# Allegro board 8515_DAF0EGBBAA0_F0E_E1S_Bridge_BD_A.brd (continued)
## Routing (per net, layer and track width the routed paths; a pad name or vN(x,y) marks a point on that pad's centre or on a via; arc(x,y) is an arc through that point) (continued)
SMB_MB_CPLD_BIC_SCL: length 7
  TOP w0.109: U35.R15 v4(133.01,32.9)
  BOTTOM w0.109: R209.2 137.52,30.99 136.31,30.99 135.81,30.48 R605.2 135.36,30.48 v1(134.61,31.22) 134.6,31.23 134.6,31.31 v4(133.01,32.9)
SMB_MB_CPLD_BIC_SDA: length 10.3
  TOP w0.109: U35.P12 v4(130.62,33.7)
  BOTTOM w0.109: R210.2 137.52,32 136.25,32 R608.2 135.03,31.5 134.82,31.71 134.57,31.71 134.23,32.05 134.23,33.09 133.21,34.1 131.02,34.1 v4(130.62,33.7)
SMB_MB_CPLD_SCL: length 9.9
  IN1 w0.124: v3(138.38,26.89) 138.47,26.98 138.47,27.27 137.97,27.76 137.97,28.06 138.17,28.26 138.91,28.26 139.03,28.39 139.03,28.99 138.91,29.11 138.01,29.11 137.88,29.23 137.88,29.7 137.98,29.79 139.12,29.79 v3(139.45,30.12)
  BOTTOM w0.109: v1(140.18,30.47) 140.01,30.3 139.63,30.3 v3(139.45,30.12) 139.09,30.48 R209.1 ; R401.1 137.33,27.09 138.19,27.09 v3(138.38,26.89)
SMB_MB_CPLD_SCL_R: length 4.1
  BOTTOM w0.109: R796.2 R401.2 137.05,25.93 R411.1 137.05,24.88 136.69,24.52 136.69,23.72 136.58,23.61 Q1.4
SMB_MB_CPLD_SDA: length 11
  IN1 w0.124: v3(134.46,28.86) 135.53,28.86 136.64,29.97 137.46,29.97 137.72,30.24 138.43,30.24 138.96,30.77 v3(139.52,30.77)
  BOTTOM w0.109: v3(139.52,30.77) 139.52,31.08 140.02,31.58 ; R210.1 138.91,31.58 140.02,31.58 ; R400.1 134.36,26.77 134.95,27.35 134.95,28.37 v3(134.46,28.86) ; 140.02,31.58 v1(140.19,31.75)
SMB_MB_CPLD_SDA_R: length 7.9
  BOTTOM w0.109: R795.2 R400.2 133.94,25.64 132.99,25.64 132.76,25.41 v1(132.76,25.13) 133.73,25.13 R410.1 133.94,24.64 134.35,24.23 134.73,24.23 134.84,24.12 134.84,23.05 134.62,22.52 134.21,22.11 Q1.1
SMB_MBBIC_BIC_R_SCL: length 3.8
  TOP w0.109: R680.1 135.38,34.54 135.25,34.67 135.25,35.79 134.8,36.24 v4(134.7,36.24) 134.67,36.22 133.95,36.22 133.66,36.5 U35.L16
SMB_MBBIC_BIC_R_SDA: length 3.3
  TOP w0.109: R681.1 135.74,35.86 134.23,37.37 v3(134.11,37.37) 134.04,37.37 133.96,37.3 U35.K16
SMB_SENSOR_SCL: length 105.6
  TOP w0.109: v3(118.49,61.47) 118.8,61.47 119.11,61.16 R277.1 118.92,60.26 117.88,60.26 117.51,59.89 R494.1
  IN1 w0.124: v3(118.49,61.47) 119.59,62.57 138.27,62.57 140.37,60.46 140.37,57.7 140.68,57.39 140.68,54.1 139.14,50.39 139.14,41.16 140.36,39.95 143.41,39.95 145.09,38.26 145.09,35.14 145.69,34.54 145.69,31.26 145.57,31.14 v3(144.9,31.14)
  BOTTOM w0.109: R290.1 95.43,48.77 100.15,44.04 105.89,44.04 109.2,47.35 109.2,48.53 109.78,49.11 111.83,49.11 113.38,50.66 113.38,52.37 115.61,54.6 116.08,54.79 116.53,55.09 117,55.57 117.33,56.37 117.33,60.6 118.2,61.47 v3(118.49,61.47) ; v3(144.9,31.14) 142.25,31.14 140.48,29.38 139.94,29.38 139.81,29.24 139.35,29.24 138.83,28.73 R584.1
SMB_SENSOR_SDA: length 243.7
  TOP w0.109: v3(39.88,13.46) 40.13,13.46 40.74,14.07 40.74,15.95 40.23,16.46 40.23,17.88 36.58,21.54 R493.1 ; R278.1 117.84,62.07 118.01,61.89 118.01,61.1 v3(118.36,60.75)
  IN1 w0.124: v3(108.08,15.62) 107.92,15.62 104.7,12.39 98.26,12.39 97.48,11.61 56.36,11.61 55.54,12.43 40.91,12.43 v3(39.88,13.46) ; v3(118.36,60.75) 118.77,60.75 120.16,62.14 138.09,62.14 139.27,60.96 139.27,57.67 139.59,57.34 140.11,57.34 140.24,57.22 140.24,54.26 138.71,50.57 138.71,40.98 140.18,39.52 143.23,39.52 144.64,38.11 144.64,38.01 144.65,38 144.65,34.83 v3(145.03,34.44)
  BOTTOM w0.109: v3(145.03,34.44) 145.36,34.11 145.36,33.17 145.01,32.82 143.73,32.82 142.46,31.55 142.08,31.55 140.31,29.79 139.77,29.79 139.64,29.66 139.02,29.66 R586.1 ; v3(108.08,15.62) 108.08,15.2 107.97,15.09 106.6,15.09 106.37,15.32 106.37,18.92 111.13,23.68 111.13,25.93 112.81,27.61 113.1,28.29 113.1,32.71 113.06,32.89 111.78,35.99 109.76,38.01 109.76,44.2 111.55,45.99 111.55,46.3 115.11,49.86 115.11,51.51 116.89,53.28 117.58,53.74 118.49,54.66 118.55,54.81 118.99,55.88 118.99,55.88 119.21,56.41 119.22,56.42 119.25,56.49 119.33,56.52 119.79,56.98 120.55,56.98 121.36,57.8 121.36,60.78 120.56,61.58 119.59,61.58 118.76,60.75 v3(118.36,60.75) 117.75,60.14 117.75,56.28 117.36,55.34 116.77,54.75 116.28,54.43 115.95,54.29 113.79,52.13 113.79,50.49 111.94,48.64 109.89,48.64 109.61,48.36 109.61,47.18 106.06,43.63 104.35,43.63 104.33,43.61 99.8,43.61 v1(96.43,46.97) 95.78,47.62 R289.1
SMB_TMP75_SCL_R: length 3.3
  TOP w0.109: U16.2 93.95,48.54 93.73,48.76 v3(93.09,48.76)
  BOTTOM w0.109: R290.2 94.42,48.82 93.32,48.82 93.26,48.76 v3(93.09,48.76)
SMB_TMP75_SDA_R: length 4.2
  TOP w0.109: v3(93.6,48.13) 93.84,47.89 U16.1
  BOTTOM w0.109: R289.2 93.81,46.96 93.37,46.96 93.24,47.09 v1(93.24,47.17) 93.24,47.78 v3(93.6,48.13)
SPI_BIC_CS0_R_N: length 6.4
  TOP w0.109: U35.A7 126.27,44.55 126.27,46.33 125.75,46.85 125.75,49.91 R635.2
SPI_BIC_R_CLK: length 6.7
  TOP w0.109: U35.A5 124.62,45.91 124.21,46.31 R789.1 124.57,46.97 124.71,47.12 124.71,49.93 R785.2
SPI_BIC_R_IO1: length 7.7
  TOP w0.109: R786.1 123.7,49.93 123.7,47.48 R782.1 123.19,46.47 124.22,45.44 124.22,44.1 U35.B5
TDR_DIFF_85_BOT_DN: length 152.4
  BOTTOM w0.132: X3.4 -9.02,19.42 -9.13,19.53 -11.32,19.53 -11.71,19.14 -11.71,17.68 -12.13,17.26 -12.72,17.26 -13.14,17.68 -13.14,21.51 -13.36,21.73 -13.67,21.73 -13.89,21.51 -13.89,17.68 -14.3,17.26 -14.89,17.26 -15.31,17.68 -15.31,21.51 -15.53,21.73 -15.84,21.73 -16.06,21.51 -16.06,17.68 -16.48,17.26 -17.07,17.26 -17.49,17.68 -17.49,21.51 -17.71,21.73 -18.01,21.73 -18.23,21.51 -18.23,17.68 -18.65,17.26 -19.24,17.26 -19.66,17.68 -19.66,21.51 -19.88,21.73 -20.19,21.73 -20.41,21.51 -20.41,17.68 -20.83,17.26 -21.42,17.26 -21.84,17.68 -21.84,21.51 -22.05,21.73 -22.36,21.73 -22.58,21.51 -22.58,17.68 -23,17.26 -23.59,17.26 -24.01,17.68 -24.01,21.51 -24.23,21.73 -24.54,21.73 -24.76,21.51 -24.76,17.68 -25.17,17.26 -25.77,17.26 -26.18,17.68 -26.18,21.51 -26.4,21.73 -26.71,21.73 -26.93,21.51 -26.93,17.68 -27.35,17.26 -27.94,17.26 -28.36,17.68 -28.36,21.51 -28.58,21.73 -28.89,21.73 -29.1,21.51 -29.1,17.68 -29.52,17.26 -30.11,17.26 -30.53,17.68 -30.53,21.51 -30.75,21.73 -31.06,21.73 -31.28,21.51 -31.28,17.68 -31.7,17.26 -32.29,17.26 -32.71,17.68 -32.71,21.51 -32.93,21.73 -33.23,21.73 -33.45,21.51 -33.45,17.68 -33.87,17.26 -34.46,17.26 -34.88,17.68 -34.88,21.51 -35.1,21.73 -35.41,21.73 -35.63,21.51 -35.63,17.68 -36.05,17.26 -36.64,17.26 -37.06,17.68 -37.06,21.51 -37.27,21.73 -37.58,21.73 -37.8,21.51 -37.8,17.68 -38.22,17.26 -38.81,17.26 -39.23,17.68 -39.23,21.51 -39.45,21.73 -39.76,21.73 -39.98,21.51 -39.98,17.68 -40.39,17.26 -40.99,17.26 -41.4,17.68 -41.4,21.51 -41.62,21.73 -41.93,21.73 -42.15,21.51 -42.15,20.04 -42.66,19.53 -45.03,19.53 -45.21,19.34 X4.1
TDR_DIFF_85_BOT_DP: length 152.4
  BOTTOM w0.132: X3.1 -9.02,19.98 -9.13,19.87 -11.46,19.87 -12.05,19.28 -12.05,17.82 -12.27,17.6 -12.58,17.6 -12.8,17.82 -12.8,21.65 -13.22,22.07 -13.81,22.07 -14.23,21.65 -14.23,17.82 -14.44,17.6 -14.75,17.6 -14.97,17.82 -14.97,21.65 -15.39,22.07 -15.98,22.07 -16.4,21.65 -16.4,17.82 -16.62,17.6 -16.93,17.6 -17.15,17.82 -17.15,21.65 -17.56,22.07 -18.16,22.07 -18.57,21.65 -18.57,17.82 -18.79,17.6 -19.1,17.6 -19.32,17.82 -19.32,21.65 -19.74,22.07 -20.33,22.07 -20.75,21.65 -20.75,17.82 -20.97,17.6 -21.28,17.6 -21.5,17.82 -21.5,21.65 -21.91,22.07 -22.5,22.07 -22.92,21.65 -22.92,17.82 -23.14,17.6 -23.45,17.6 -23.67,17.82 -23.67,21.65 -24.09,22.07 -24.68,22.07 -25.1,21.65 -25.1,17.82 -25.32,17.6 -25.62,17.6 -25.84,17.82 -25.84,21.65 -26.26,22.07 -26.85,22.07 -27.27,21.65 -27.27,17.82 -27.49,17.6 -27.8,17.6 -28.02,17.82 -28.02,21.65 -28.44,22.07 -29.03,22.07 -29.45,21.65 -29.45,17.82 -29.66,17.6 -29.97,17.6 -30.19,17.82 -30.19,21.65 -30.61,22.07 -31.2,22.07 -31.62,21.65 -31.62,17.82 -31.84,17.6 -32.15,17.6 -32.37,17.82 -32.37,21.65 -32.78,22.07 -33.38,22.07 -33.79,21.65 -33.79,17.82 -34.01,17.6 -34.32,17.6 -34.54,17.82 -34.54,21.65 -34.96,22.07 -35.55,22.07 -35.97,21.65 -35.97,17.82 -36.19,17.6 -36.5,17.6 -36.71,17.82 -36.71,21.65 -37.13,22.07 -37.72,22.07 -38.14,21.65 -38.14,17.82 -38.36,17.6 -38.67,17.6 -38.89,17.82 -38.89,21.65 -39.31,22.07 -39.9,22.07 -40.32,21.65 -40.32,17.82 -40.54,17.6 -40.84,17.6 -41.06,17.82 -41.06,21.65 -41.48,22.07 -42.07,22.07 -42.49,21.65 -42.49,20.18 -42.81,19.87 -45.03,19.87 -45.21,20.05 X4.4
TDR_DIFF_85_IN1_DN: length 152.4
  IN1 w0.155: X6.4 -8.67,115.62 -8.74,115.55 -10.6,115.55 -10.75,115.69 -10.75,117.42 -11.24,117.91 -11.94,117.91 -12.43,117.42 -12.43,113.48 -12.72,113.19 -13.12,113.19 -13.41,113.48 -13.41,117.42 -13.9,117.91 -14.6,117.91 -15.1,117.42 -15.1,113.48 -15.38,113.19 -15.78,113.19 -16.07,113.48 -16.07,117.42 -16.56,117.91 -17.26,117.91 -17.76,117.42 -17.76,113.48 -18.04,113.19 -18.45,113.19 -18.73,113.48 -18.73,117.42 -19.23,117.91 -19.93,117.91 -20.42,117.42 -20.42,113.48 -20.71,113.19 -21.11,113.19 -21.39,113.48 -21.39,117.42 -21.89,117.91 -22.59,117.91 -23.08,117.42 -23.08,113.48 -23.37,113.19 -23.77,113.19 -24.06,113.48 -24.06,117.42 -24.55,117.91 -25.25,117.91 -25.74,117.42 -25.74,113.48 -26.03,113.19 -26.43,113.19 -26.72,113.48 -26.72,117.42 -27.21,117.91 -27.91,117.91 -28.41,117.42 -28.41,113.48 -28.69,113.19 -29.09,113.19 -29.38,113.48 -29.38,117.42 -29.87,117.91 -30.57,117.91 -31.07,117.42 -31.07,113.48 -31.35,113.19 -31.76,113.19 -32.04,113.48 -32.04,117.42 -32.54,117.91 -33.24,117.91 -33.73,117.42 -33.73,113.48 -34.02,113.19 -34.42,113.19 -34.7,113.48 -34.7,117.42 -35.2,117.91 -35.9,117.91 -36.39,117.42 -36.39,113.48 -36.68,113.19 -37.08,113.19 -37.36,113.48 -37.36,117.42 -37.86,117.91 -38.56,117.91 -39.05,117.42 -39.05,113.48 -39.34,113.19 -39.74,113.19 -40.03,113.48 -40.03,117.42 -40.52,117.91 -41.22,117.91 -41.72,117.42 -41.72,113.48 -42,113.19 -42.4,113.19 -42.69,113.48 -42.69,117.42 -43.18,117.91 -43.88,117.91 -44.38,117.42 -44.38,113.48 -44.66,113.19 -45.07,113.19 -45.35,113.48 -45.35,114.82 -46.08,115.55 -48.47,115.55 -48.67,115.75 X5.1
TDR_DIFF_85_IN1_DP: length 152.4
  IN1 w0.155: X5.4 -48.67,114.99 -48.47,115.19 -46.23,115.19 -45.71,114.67 -45.71,113.33 -45.21,112.83 -44.51,112.83 -44.02,113.33 -44.02,117.27 -43.73,117.55 -43.33,117.55 -43.05,117.27 -43.05,113.33 -42.55,112.83 -41.85,112.83 -41.36,113.33 -41.36,117.27 -41.07,117.55 -40.67,117.55 -40.38,117.27 -40.38,113.33 -39.89,112.83 -39.19,112.83 -38.7,113.33 -38.7,117.27 -38.41,117.55 -38.01,117.55 -37.72,117.27 -37.72,113.33 -37.23,112.83 -36.53,112.83 -36.03,113.33 -36.03,117.27 -35.75,117.55 -35.35,117.55 -35.06,117.27 -35.06,113.33 -34.57,112.83 -33.87,112.83 -33.37,113.33 -33.37,117.27 -33.09,117.55 -32.68,117.55 -32.4,117.27 -32.4,113.33 -31.9,112.83 -31.2,112.83 -30.71,113.33 -30.71,117.27 -30.43,117.55 -30.02,117.55 -29.74,117.27 -29.74,113.33 -29.24,112.83 -28.54,112.83 -28.05,113.33 -28.05,117.27 -27.76,117.55 -27.36,117.55 -27.08,117.27 -27.08,113.33 -26.58,112.83 -25.88,112.83 -25.39,113.33 -25.39,117.27 -25.1,117.55 -24.7,117.55 -24.41,117.27 -24.41,113.33 -23.92,112.83 -23.22,112.83 -22.72,113.33 -22.72,117.27 -22.44,117.55 -22.04,117.55 -21.75,117.27 -21.75,113.33 -21.26,112.83 -20.56,112.83 -20.06,113.33 -20.06,117.27 -19.78,117.55 -19.37,117.55 -19.09,117.27 -19.09,113.33 -18.6,112.83 -17.9,112.83 -17.4,113.33 -17.4,117.27 -17.12,117.55 -16.71,117.55 -16.43,117.27 -16.43,113.33 -15.93,112.83 -15.23,112.83 -14.74,113.33 -14.74,117.27 -14.45,117.55 -14.05,117.55 -13.77,117.27 -13.77,113.33 -13.27,112.83 -12.57,112.83 -12.08,113.33 -12.08,117.27 -11.79,117.55 -11.39,117.55 -11.1,117.27 -11.1,115.54 -10.75,115.19 -8.74,115.19 -8.67,115.12 X6.1
TDR_DIFF_85_IN2_DN: length 152.4
  IN2 w0.155: X7.4 -48.67,121.47 -48.47,121.27 -46.08,121.27 -45.35,120.54 -45.35,119.19 -45.07,118.91 -44.66,118.91 -44.38,119.19 -44.38,123.13 -43.88,123.63 -43.18,123.63 -42.69,123.13 -42.69,119.19 -42.4,118.91 -42,118.91 -41.72,119.19 -41.72,123.13 -41.22,123.63 -40.52,123.63 -40.03,123.13 -40.03,119.19 -39.74,118.91 -39.34,118.91 -39.05,119.19 -39.05,123.13 -38.56,123.63 -37.86,123.63 -37.36,123.13 -37.36,119.19 -37.08,118.91 -36.68,118.91 -36.39,119.19 -36.39,123.13 -35.9,123.63 -35.2,123.63 -34.7,123.13 -34.7,119.19 -34.42,118.91 -34.02,118.91 -33.73,119.19 -33.73,123.13 -33.24,123.63 -32.54,123.63 -32.04,123.13 -32.04,119.19 -31.76,118.91 -31.35,118.91 -31.07,119.19 -31.07,123.13 -30.57,123.63 -29.87,123.63 -29.38,123.13 -29.38,119.19 -29.09,118.91 -28.69,118.91 -28.41,119.19 -28.41,123.13 -27.91,123.63 -27.21,123.63 -26.72,123.13 -26.72,119.19 -26.43,118.91 -26.03,118.91 -25.74,119.19 -25.74,123.13 -25.25,123.63 -24.55,123.63 -24.06,123.13 -24.06,119.19 -23.77,118.91 -23.37,118.91 -23.08,119.19 -23.08,123.13 -22.59,123.63 -21.89,123.63 -21.39,123.13 -21.39,119.19 -21.11,118.91 -20.71,118.91 -20.42,119.19 -20.42,123.13 -19.93,123.63 -19.23,123.63 -18.73,123.13 -18.73,119.19 -18.45,118.91 -18.04,118.91 -17.76,119.19 -17.76,123.13 -17.26,123.63 -16.56,123.63 -16.07,123.13 -16.07,119.19 -15.78,118.91 -15.38,118.91 -15.1,119.19 -15.1,123.13 -14.6,123.63 -13.9,123.63 -13.41,123.13 -13.41,119.19 -13.12,118.91 -12.72,118.91 -12.43,119.19 -12.43,123.13 -11.94,123.63 -11.24,123.63 -10.75,123.13 -10.75,121.41 -10.6,121.27 -8.74,121.27 -8.67,121.34 X8.1
TDR_DIFF_85_IN2_DP: length 152.4
  IN2 w0.155: X7.1 -48.67,120.71 -48.47,120.91 -46.23,120.91 -45.71,120.39 -45.71,119.04 -45.21,118.55 -44.51,118.55 -44.02,119.04 -44.02,122.98 -43.73,123.27 -43.33,123.27 -43.05,122.98 -43.05,119.04 -42.55,118.55 -41.85,118.55 -41.36,119.04 -41.36,122.98 -41.07,123.27 -40.67,123.27 -40.38,122.98 -40.38,119.04 -39.89,118.55 -39.19,118.55 -38.7,119.04 -38.7,122.98 -38.41,123.27 -38.01,123.27 -37.72,122.98 -37.72,119.04 -37.23,118.55 -36.53,118.55 -36.03,119.04 -36.03,122.98 -35.75,123.27 -35.35,123.27 -35.06,122.98 -35.06,119.04 -34.57,118.55 -33.87,118.55 -33.37,119.04 -33.37,122.98 -33.09,123.27 -32.68,123.27 -32.4,122.98 -32.4,119.04 -31.9,118.55 -31.2,118.55 -30.71,119.04 -30.71,122.98 -30.43,123.27 -30.02,123.27 -29.74,122.98 -29.74,119.04 -29.24,118.55 -28.54,118.55 -28.05,119.04 -28.05,122.98 -27.76,123.27 -27.36,123.27 -27.08,122.98 -27.08,119.04 -26.58,118.55 -25.88,118.55 -25.39,119.04 -25.39,122.98 -25.1,123.27 -24.7,123.27 -24.41,122.98 -24.41,119.04 -23.92,118.55 -23.22,118.55 -22.72,119.04 -22.72,122.98 -22.44,123.27 -22.04,123.27 -21.75,122.98 -21.75,119.04 -21.26,118.55 -20.56,118.55 -20.06,119.04 -20.06,122.98 -19.78,123.27 -19.37,123.27 -19.09,122.98 -19.09,119.04 -18.6,118.55 -17.9,118.55 -17.4,119.04 -17.4,122.98 -17.12,123.27 -16.71,123.27 -16.43,122.98 -16.43,119.04 -15.93,118.55 -15.23,118.55 -14.74,119.04 -14.74,122.98 -14.45,123.27 -14.05,123.27 -13.77,122.98 -13.77,119.04 -13.27,118.55 -12.57,118.55 -12.08,119.04 -12.08,122.98 -11.79,123.27 -11.39,123.27 -11.1,122.98 -11.1,121.26 -10.75,120.91 -8.74,120.91 -8.67,120.84 X8.4
TDR_DIFF_85_TOP_DN: length 152.4
  TOP w0.132: X2.1 -45.21,14.34 -45.03,14.15 -42.81,14.15 -42.49,14.47 -42.49,15.94 -42.07,16.36 -41.48,16.36 -41.06,15.94 -41.06,12.1 -40.84,11.89 -40.54,11.89 -40.32,12.1 -40.32,15.94 -39.9,16.36 -39.31,16.36 -38.89,15.94 -38.89,12.1 -38.67,11.89 -38.36,11.89 -38.14,12.1 -38.14,15.94 -37.72,16.36 -37.13,16.36 -36.71,15.94 -36.71,12.1 -36.5,11.89 -36.19,11.89 -35.97,12.1 -35.97,15.94 -35.55,16.36 -34.96,16.36 -34.54,15.94 -34.54,12.1 -34.32,11.89 -34.01,11.89 -33.79,12.1 -33.79,15.94 -33.38,16.36 -32.78,16.36 -32.37,15.94 -32.37,12.1 -32.15,11.89 -31.84,11.89 -31.62,12.1 -31.62,15.94 -31.2,16.36 -30.61,16.36 -30.19,15.94 -30.19,12.1 -29.97,11.89 -29.66,11.89 -29.45,12.1 -29.45,15.94 -29.03,16.36 -28.44,16.36 -28.02,15.94 -28.02,12.1 -27.8,11.89 -27.49,11.89 -27.27,12.1 -27.27,15.94 -26.85,16.36 -26.26,16.36 -25.84,15.94 -25.84,12.1 -25.62,11.89 -25.32,11.89 -25.1,12.1 -25.1,15.94 -24.68,16.36 -24.09,16.36 -23.67,15.94 -23.67,12.1 -23.45,11.89 -23.14,11.89 -22.92,12.1 -22.92,15.94 -22.5,16.36 -21.91,16.36 -21.5,15.94 -21.5,12.1 -21.28,11.89 -20.97,11.89 -20.75,12.1 -20.75,15.94 -20.33,16.36 -19.74,16.36 -19.32,15.94 -19.32,12.1 -19.1,11.89 -18.79,11.89 -18.57,12.1 -18.57,15.94 -18.16,16.36 -17.56,16.36 -17.15,15.94 -17.15,12.1 -16.93,11.89 -16.62,11.89 -16.4,12.1 -16.4,15.94 -15.98,16.36 -15.39,16.36 -14.97,15.94 -14.97,12.1 -14.75,11.89 -14.44,11.89 -14.23,12.1 -14.23,15.94 -13.81,16.36 -13.22,16.36 -12.8,15.94 -12.8,12.1 -12.58,11.89 -12.27,11.89 -12.05,12.1 -12.05,13.56 -11.46,14.15 -9.13,14.15 -9.02,14.26 X1.4
TDR_DIFF_85_TOP_DP: length 152.4
  TOP w0.132: X1.1 -9.02,13.7 -9.13,13.81 -11.32,13.81 -11.71,13.42 -11.71,11.96 -12.13,11.55 -12.72,11.55 -13.14,11.96 -13.14,15.8 -13.36,16.02 -13.67,16.02 -13.89,15.8 -13.89,11.96 -14.3,11.55 -14.89,11.55 -15.31,11.96 -15.31,15.8 -15.53,16.02 -15.84,16.02 -16.06,15.8 -16.06,11.96 -16.48,11.55 -17.07,11.55 -17.49,11.96 -17.49,15.8 -17.71,16.02 -18.01,16.02 -18.23,15.8 -18.23,11.96 -18.65,11.55 -19.24,11.55 -19.66,11.96 -19.66,15.8 -19.88,16.02 -20.19,16.02 -20.41,15.8 -20.41,11.96 -20.83,11.55 -21.42,11.55 -21.84,11.96 -21.84,15.8 -22.05,16.02 -22.36,16.02 -22.58,15.8 -22.58,11.96 -23,11.55 -23.59,11.55 -24.01,11.96 -24.01,15.8 -24.23,16.02 -24.54,16.02 -24.76,15.8 -24.76,11.96 -25.17,11.55 -25.77,11.55 -26.18,11.96 -26.18,15.8 -26.4,16.02 -26.71,16.02 -26.93,15.8 -26.93,11.96 -27.35,11.55 -27.94,11.55 -28.36,11.96 -28.36,15.8 -28.58,16.02 -28.89,16.02 -29.1,15.8 -29.1,11.96 -29.52,11.55 -30.11,11.55 -30.53,11.96 -30.53,15.8 -30.75,16.02 -31.06,16.02 -31.28,15.8 -31.28,11.96 -31.7,11.55 -32.29,11.55 -32.71,11.96 -32.71,15.8 -32.93,16.02 -33.23,16.02 -33.45,15.8 -33.45,11.96 -33.87,11.55 -34.46,11.55 -34.88,11.96 -34.88,15.8 -35.1,16.02 -35.41,16.02 -35.63,15.8 -35.63,11.96 -36.05,11.55 -36.64,11.55 -37.06,11.96 -37.06,15.8 -37.27,16.02 -37.58,16.02 -37.8,15.8 -37.8,11.96 -38.22,11.55 -38.81,11.55 -39.23,11.96 -39.23,15.8 -39.45,16.02 -39.76,16.02 -39.98,15.8 -39.98,11.96 -40.39,11.55 -40.99,11.55 -41.4,11.96 -41.4,15.8 -41.62,16.02 -41.93,16.02 -42.15,15.8 -42.15,14.33 -42.66,13.81 -45.03,13.81 -45.21,13.63 X2.4
TDR_SE_50_OHM_BOT: length 152.5
  BOTTOM w0.109: J15.3 -35.93,29.76 -35.83,29.65 -33.5,29.65 -33.39,29.76 J15.2
TDR_SE_50_OHM_IN1: length 152.5
  IN1 w0.124: J12.3 -40.71,29.76 -40.82,29.65 -43.14,29.65 -43.25,29.76 J12.2
TDR_SE_50_OHM_IN2: length 152.5
  IN2 w0.124: J16.3 -50.57,29.76 -50.46,29.65 -48.14,29.65 -48.03,29.76 J16.2
TDR_SE_50_OHM_TOP: length 152.5
  TOP w0.109: J27.2 -57.78,29.76 -57.67,29.65 -55.35,29.65 -55.24,29.76 J27.3
TMP75_AD0: length 4.2
  TOP w0.109: R294.1 R288.2 88.7,47.47 v2(88.7,48.64) 88.79,48.54 U16.7
TMP75_AD1: length 5.7
  TOP w0.109: U16.6 89.24,49.19 89.03,49.4 v3(88.27,49.4)
  BOTTOM w0.109: R293.1 R287.2 90.05,49 89.56,49 89.15,49.4 v3(88.27,49.4)
TMP75_AD2: length 4.2
  TOP w0.109: U16.5 89.75,49.84 v3(89.1,50.5)
  BOTTOM w0.109: v3(89.1,50.5) 89.1,50.47 89.66,49.91 R286.2 R292.1
TMP75_ALERT_N_R: length 4.9
  TOP w0.109: U16.3 94.17,49.19 93.94,49.42 93.94,50.28 v3(94.12,50.46)
  BOTTOM w0.109: R295.1 93.57,49.91 v3(94.12,50.46) 94.13,50.46 94.68,49.91 R291.2
TP_CLK_100M_E1S_0_DN: length 4.5
  TOP w0.109: v2(36.83,35.56) 36.58,35.81 35.15,35.81 34.62,36.35 33.91,36.35 33.56,36.69 J4.A14
TP_CLK_100M_E1S_0_DP: length 4
  TOP w0.109: J4.A15 33.5,36.09 33.73,35.86 34.47,35.86 v2(36.06,34.28)
TP_CLK_100M_E1S_1_DN: length 6.4
  TOP w0.109: v2(63.63,36.83) 63.63,36.7 63.53,36.61 63.28,36.61 62.28,35.61 62.28,35.61 62.23,35.56 60.07,35.56 58.94,36.7 J5.A14
TP_CLK_100M_E1S_1_DP: length 3.8
  TOP w0.109: J5.A15 58.9,36.1 60.2,34.8 v2(61.59,34.8)
TP_CLK_100M_E1S_2_DN: length 3.7
  TOP w0.109: J6.A14 84.63,36.7 84.72,36.6 85.5,36.6 86.51,35.59 v2(87.07,35.59)
TP_CLK_100M_E1S_2_DP: length 4.8
  TOP w0.109: v2(87.38,33.78) 87.38,34.19 85.39,36.17 84.7,36.17 84.63,36.1 J6.A15
TP_CLK_100M_E1S_3_DN: length 2.1
  TOP w0.109: J7.A14 108.11,36.7 v3(107.48,37.33)
TP_CLK_100M_E1S_3_DP: length 4.1
  TOP w0.109: J7.A15 108.13,36.1 107.49,36.73 106.18,36.73 106.03,36.88 v3(106.03,37.33)
TP_E1S_0_MFG: length 2.8
  TOP w0.109: v3(26.42,40.31) 27,40.89 J4.B7
  BOTTOM w0.109: v1(26.21,41.02) 26.21,40.54 26.41,40.33 v3(26.42,40.31)
TP_E1S_0_RFU: length 1.9
  TOP w0.109: J4.B8 v3(27.09,40.29)
  BOTTOM w0.109: v3(27.09,40.29) 27.6,40.29 27.76,40.46 v1(27.78,40.46)
TP_E1S_1_MFG: length 5.5
  TOP w0.109: v2(48.56,41.48) 48.74,41.66 49.99,41.66 50.75,40.9 J5.B7
TP_E1S_1_RFU: length 4
  TOP w0.109: v2(49.91,40.89) 50.16,40.89 50.55,40.51 52.83,40.51 53.05,40.3 J5.B8
TP_E1S_2_MFG: length 5.2
  TOP w0.109: v2(75.31,42.8) 75.31,41.91 76.33,40.9 J6.B7
TP_E1S_2_RFU: length 4.1
  TOP w0.109: J6.B8 76.04,40.3 75.56,40.77 v2(75.31,40.77)
TP_E1S_3_MFG: length 4.7
  TOP w0.109: J7.B7 102.74,40.9 102.18,40.33 100.63,40.33 v2(100.36,40.06)
TP_E1S_3_RFU: length 5.5
  TOP w0.109: J7.B8 102.91,40.3 102.58,39.97 101.13,39.97 100.47,39.3 v2(99.64,38.96)
TP_P12V_E1S_0_PG: length 0.8
  TOP w0.109: v3(20.11,56.55) 19.71,56.95 U22.D7
TP_P12V_E1S_1_PG: length 0.8
  TOP w0.109: v3(44.63,56) 44.59,56 44.48,56.11 U23.D7
TP_P12V_E1S_2_PG: length 0.8
  TOP w0.109: U24.D7 70,55.8 v3(70.17,55.64)
TP_P12V_E1S_3_PG: length 0.8
  TOP w0.109: U25.D7 95.48,56.33 v3(95.95,55.86)
UART_BIC5_R_RXD: length 55.4
  TOP w0.109: J1.3 141.86,31.69 141.75,31.8 141.64,31.8 v3(141.57,31.86) ; v3(135.71,54.49) 135.42,54.2 134.99,54.2 134.05,53.26 134.05,52.28 134.62,51.71 135.13,50.49 135.13,47.17 134.93,46.97 R691.1 134.62,46.79 132.69,44.86 132.17,44.86 U35.A14
  IN2 w0.124: J30.1 140.36,60.31 140.36,56.4 139.92,55.96 138.42,55.96 137.9,56.47 134.75,56.47 134.63,56.35 134.63,55.46 135.6,54.49 v3(135.71,54.49) 137.84,54.49 138.4,53.93 138.4,47.14 137.78,46.52 137.78,41.9 138.2,41.48 138.2,40.28 139.01,39.48 139.01,35.99 141.34,33.66 141.34,33.17 141.57,32.94 v3(141.57,31.86)
UART_BIC5_R_TXD: length 8.4
  TOP w0.109: R590.1 138.83,37.87 138.94,37.98 139.74,37.98 R679.2 139.82,37.46 139.8,37.44 139.8,36.15 140.25,35.7 J1.1 143.22,35.7 v3(143.69,36.17)
UART_BIC_TXD: length 20.2
  TOP w0.109: v3(140.92,37.31) 140.92,38.36 140.57,38.71 R679.1 ; U35.D13 v4(131.42,42.5)
  IN1 w0.124: v4(131.42,42.5) 131.81,42.1 133.04,42.1 134.9,40.24 134.9,38.81 135.81,37.9 137.22,37.9 137.81,37.31 v3(140.92,37.31)
  BOTTOM w0.109: v3(140.92,37.31) 141.8,38.2 R776.1 R780.2
UART_HOST_RXD: length 8.4
  TOP w0.109: R591.2 135.64,36.58 134.11,38.1 v3(134.03,38.1) ; U35.F12 v4(130.62,40.9)
  BOTTOM w0.109: v3(134.03,38.1) 132.51,38.1 v1(132.17,38.45) 131.83,38.79 131.83,39.57 131.67,39.73 131.14,39.73 131.01,39.85 131.01,40.67 130.78,40.9 v4(130.62,40.9)
UART_HOST_TXD: length 16.8
  TOP w0.109: R690.2 134.53,50.44 134.41,50.56 134.41,51.15 134.24,51.55 133.67,52.12 133.67,52.65 v3(133.42,52.89) ; U35.E12 v4(130.62,41.7)
  BOTTOM w0.109: v3(133.42,52.89) 133.01,52.48 133.01,50.83 133.08,50.76 133.08,46.11 132.35,45.38 132.21,45.38 132.16,45.33 131.07,45.33 130.87,45.14 130.87,44.56 131.02,44.41 131.02,42.1 v4(130.62,41.7)
UART_MB_RX: length 150.2
  TOP w0.109: v3(141.88,33.42) 141.65,33.42 139.41,35.65 139.41,35.91 139.28,36.04 138.25,36.04 138.03,36.26 R590.2 R591.1
  IN2 w0.124: v3(27.43,8.13) 27.05,8.51 27.05,9.45 27.44,9.84 30.95,9.84 31.06,9.73 50.03,9.73 50.64,9.74 51.22,9.63 64.99,9.63 65.17,9.45 85.4,9.45 85.71,9.13 97.67,9.13 98.28,9.75 128.92,9.75 131.51,12.33 131.51,15.99 132.39,16.88 132.39,21.65 133.02,22.28 134.15,22.28 135.24,23.37 136.04,23.37 136.88,24.21 136.88,24.71 137.36,25.2 138.25,25.2 138.88,24.57 140.13,24.57 140.84,25.29 140.84,26.6 141.26,27.02 141.26,28.91 140.98,29.2 140.98,30.39 142.17,31.58 142.17,33.13 v3(141.88,33.42)
  BOTTOM w0.109: GF1.A14 27.65,7.91 v3(27.43,8.13)
UART_MB_TX: length 181.9
  TOP w0.109: R691.2 134.71,47.87 134.71,49.54 R690.1 134.33,49.64 134.02,49.95 134.02,51.06 133.91,51.34 132.94,52.31 132.94,53.14 133.78,53.98 134.2,53.98 134.8,54.58 135.09,54.58 135.36,54.85 135.36,55.91 v3(135.31,55.96)
  IN2 w0.124: v3(30.76,9.37) 30.83,9.3 50.03,9.3 50.6,9.31 51.18,9.2 64.81,9.2 65,9.02 85.22,9.02 85.53,8.7 97.85,8.7 98.46,9.32 129.13,9.32 131.95,12.14 131.95,15.72 132.96,16.73 132.96,19.99 133.45,20.48 133.94,20.48 134.56,21.09 134.56,21.98 135.46,22.89 138.12,22.89 139.34,24.1 140.36,24.1 141.35,25.1 141.35,26.51 141.69,26.84 141.69,29.09 141.44,29.34 141.44,30.21 142.67,31.44 142.67,34.04 139.66,37.05 139.66,39.71 138.63,40.74 138.63,41.66 138.21,42.08 138.21,46.09 138.97,46.85 138.97,54.06 138.07,54.96 136.3,54.96 v3(135.31,55.96) 137.56,55.96 138.06,55.45 140.06,55.45 141.45,56.85 J30.2
  BOTTOM w0.109: v3(30.76,9.37) 30.76,9.8 31.44,10.49 v1(31.44,11.64) 31.44,12.39 R17.2
UART_MB_TX_R: length 11.7
  BOTTOM w0.109: GF1.A15 28.25,8.19 v1(30.46,10.39) 30.46,11.28 30.21,11.54 R17.1
USB2_FT232_BIC_DN: length 82.8
  BOTTOM w0.132: R560.1 118.13,42.46 116.96,42.46 113.61,39.11 113.61,36.16 114.84,33.21 114.84,26.43 113.26,24.86 113.26,23.9 112.23,22.88 112.23,21.43 111.64,20.84 110.12,20.2 109.49,19.26 109.49,15.38 109.87,15 109.87,14.24 106.65,11.02 105.25,10.29 90.82,7.75 86.53,8.5 81.67,8.5 79.34,8.09 77.54,8.41 75.66,8.74 72.71,8.22 v4(70.72,7.87) 69.2,7.6 67.97,5.84 67.89,5.44 67.89,3.3 67.77,3.18 GF1.A68
USB2_FT232_BIC_DP: length 82.7
  BOTTOM w0.132: GF1.A69 68.37,3.16 68.23,3.3 68.23,5.41 68.29,5.7 69.4,7.29 70.77,7.53 72.77,7.89 75.66,8.4 77.48,8.08 79.34,7.75 81.7,8.16 86.5,8.16 90.82,7.4 105.36,9.97 106.86,10.75 v4(109.68,13.57) 110.21,14.1 110.21,15.14 109.83,15.52 109.83,17.76 110.04,17.97 110.04,18.35 109.83,18.56 109.83,19.16 110.34,19.93 111.83,20.55 112.57,21.29 112.57,22.73 113.6,23.76 113.6,24.72 115.18,26.29 115.18,33.28 113.95,36.23 113.95,38.97 115.15,40.17 115.45,40.17 115.72,40.44 115.72,40.73 115.98,41 116.28,41 116.55,41.27 116.55,41.56 117.1,42.12 118.13,42.12 R559.1
USB_DN: length 6.4
  TOP w0.132: U35.F4 v4(124.22,40.9)
  BOTTOM w0.102: v4(124.22,40.9) 124.13,40.88 123.75,41.14 123.57,41.32 123.37,41.4 123.08,41.4 122.92,41.24 121.35,41.24 121.19,41.41 121.19,41.5 121.17,41.52
  BOTTOM w0.132: 121.17,41.52 120.07,42.62 119.45,42.62 R560.2
USB_DP: length 6.4
  TOP w0.132: U35.E4 v4(123.42,40.9)
  BOTTOM w0.102: v4(123.42,40.9) 123.47,40.95 123.47,41.1 123.4,41.17 123.33,41.2 123.17,41.2 123,41.04 122.79,41.04 122.69,40.94 122.49,40.94 122.39,41.04 122.06,41.04 121.96,40.94 121.76,40.94 121.66,41.04 121.27,41.04 121.05,41.26 120.95,41.26 120.93,41.28
  BOTTOM w0.132: 120.93,41.28 120.66,41.55 120.37,41.55 120.19,41.73 120.19,42.02 119.93,42.28 119.4,42.28 119.27,42.15 R559.2

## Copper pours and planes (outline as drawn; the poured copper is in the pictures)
GND on TOP (solid shape): 1.02,22.83 0.51,22.83 0.51,39.6 1.02,39.6
GND on TOP (solid shape): 33.45,44.81 33.45,41.35 31.71,41.35 31.1,41.96 31.1,44.65 31.38,44.93 33.32,44.93
GND on TOP (solid shape): 84.44,44.5 84.44,41.36 82.7,41.36 82.09,41.97 82.09,43.75 83.07,44.73 84.21,44.73
GND on TOP (solid shape): 12.95,20.35 12.95,15.04 12.84,14.92 9.52,14.92 9.05,15.4 9.05,20.31 9.29,20.56 12.74,20.56
GND on TOP (solid shape): 16.74,62.41 16.74,61.01 16.61,60.88 15.2,60.88 14.53,61.56 14.53,62.48 14.64,62.6 16.55,62.6
GND on TOP (solid shape): 20.7,38.94 20.7,37.47 20.6,37.37 18.62,37.37 18.52,37.47 18.52,39.14 18.64,39.27 20.37,39.27
GND on TOP (solid shape): 39.14,54.97 39.14,52.6 39.01,52.48 37.36,52.48 37.31,52.53 37.31,55.04 37.47,55.19 38.91,55.19
GND on TOP (solid shape): 48.77,40.54 48.77,38.51 48.62,38.35 47.07,38.35 46.99,38.43 46.99,40.62 47.07,40.69 48.62,40.69
GND on TOP (solid shape): 64.67,53.98 64.67,51.61 64.54,51.49 62.89,51.49 62.84,51.54 62.84,54.05 62.99,54.2 64.44,54.2
GND on TOP (solid shape): 66.85,62.33 66.85,60.43 66.73,60.3 64.44,60.3 64.31,60.43 64.31,62.33 64.44,62.46 66.73,62.46
GND on TOP (solid shape): 72.39,52.07 72.39,51.26 72.16,51.03 69.57,51.03 69.39,51.21 69.39,52.12 69.68,52.41 72.05,52.41
GND on TOP (solid shape): 90.14,54.13 90.14,51.77 90.02,51.64 88.37,51.64 88.32,51.69 88.32,54.2 88.47,54.36 89.92,54.36
GND on TOP (solid shape): 92.16,62.53 92.16,61.13 91.99,60.96 89.89,60.96 89.79,61.06 89.79,62.48 89.92,62.61 92.08,62.61
GND on TOP (solid shape): 97.27,28.87 97.27,26.63 97.05,26.42 95.91,26.42 95.76,26.57 95.76,28.8 95.91,28.96 97.18,28.96
GND on TOP (solid shape): 127.84,12.09 127.84,10.59 127.53,10.29 122.5,10.29 122.38,10.41 122.38,12.27 122.64,12.53 127.39,12.53
GND on TOP (solid shape): 14.35,37.72 14.35,36.07 14.22,35.94 12.78,35.94 12.78,37.57 13.18,37.97 14.1,37.97
GND on TOP (solid shape): 58.92,44.83 58.92,41.38 57.18,41.38 56.98,41.57 56.98,41.85 56.57,42.27 56.57,44.68 56.85,44.96 58.79,44.96
GND on TOP (solid shape): 62.13,25.17 62.13,22.38 62.05,22.3 61.7,22.3 61.54,22.46 61.54,25.21 61.71,25.37 61.93,25.37
GND on TOP (solid shape): 124.88,21.93 124.97,21.42 124.97,21.18 124.61,20.83 122.78,20.83 122.68,20.93 122.68,21.89 122.78,22 124.82,22
GND on TOP (solid shape): 70.26,21.16 70.26,19.89 70.12,19.75 70.12,19.62 69.85,19.35 68.76,19.35 68.61,19.51 68.61,21.11 68.76,21.26 70.15,21.26
GND on TOP (solid shape): 109.93,44.61 109.93,41.37 109.83,41.27 108.71,41.27 108.58,41.4 108.58,42.29 108.08,42.8 108.08,44.34 108.38,44.64 109.89,44.64
GND on TOP (solid shape): 125.35,25.73 125.35,22.48 125.22,22.35 123.7,22.35 123.57,22.48 123.57,23.06 123.71,23.2 123.71,25.79 123.75,25.83 125.25,25.83
GND on TOP (solid shape): 41.33,62.31 41.33,60.4 41.2,60.27 39.8,60.27 39.8,60.28 39.69,60.28 39.37,60.59 39.37,62.18 39.62,62.43 41.2,62.43
GND on TOP (solid shape): 5.47,38.24 5.47,37.54 5.47,37.47 5.49,37.4 5.49,35 5.33,34.85 1.42,34.85 1.29,34.98 1.29,38.21 1.44,38.36 5.35,38.36
GND on TOP (solid shape): 15.62,46.75 15.62,46.15 15.52,46.05 14.91,46.05 14.83,45.97 14.83,44.65 14.78,44.6 13.97,44.6 13.94,44.63 13.94,46.81 14.03,46.9 15.47,46.9
GND on TOP (solid shape): 70.8,59.4 70.8,57.26 70.7,57.16 69.91,57.16 69.82,57.25 69.82,57.95 70.22,58.35 70.22,58.95 69.81,59.36 69.44,59.36 69.44,60.07 70.13,60.07
GND on TOP (solid shape): 95.17,34.29 95.17,34.06 94.69,33.58 93.85,33.58 93.73,33.45 93.73,31.83 93.65,31.75 93.04,31.75 92.91,31.88 92.91,34.44 92.94,34.47 95,34.47
GND on TOP (solid shape): 117.98,26.04 117.98,24.64 117.86,24.51 116.23,24.51 116.23,24.77 116.23,24.83 116.21,24.89 115.95,25.51 115.95,26.04 116.08,26.16 117.86,26.16
GND on TOP (solid shape): 96.39,60.17 96.39,58.51 96.72,58.18 96.72,57.37 96.45,57.09 95.84,57.09 95.6,57.34 95.41,57.34 95.34,57.4 95.34,58.08 95.76,58.5 95.76,59.49 95.83,59.56 95.83,60.22 96.34,60.22
GND on TOP (solid shape): 129.2,25.1 130.68,25.1 130.94,24.84 130.94,23.6 130.81,23.47 128.87,23.47 128.71,23.62 128.71,24.83 128.02,25.53 128.02,25.78 128.1,25.87 128.42,25.87
GND on TOP (solid shape): 44.86,45.49 44.86,44.58 44.27,43.99 43.64,43.99 43.51,43.87 43.51,42.57 43.43,42.49 42.7,42.49 42.62,42.57 42.62,45.11 43.13,45.62 44.73,45.62
GND on TOP (solid shape): 119.37,18.55 119.96,18.55 120.07,18.67 120.22,18.67 120.29,18.59 120.29,18.03 120.4,17.93 121.72,17.93 121.74,17.91 121.74,17.17 121.67,17.09 117.83,17.09 117.71,17.22 117.71,18.38 118,18.67 119.25,18.67
GND on TOP (solid shape): 14.99,55.47 14.99,53.16 14.83,53.01 12.8,53.01 12.52,53.29 12.52,54.15 12.56,54.26 12.57,54.38 12.57,54.74 12.56,54.85 12.52,54.96 12.52,55.37 12.83,55.68 14.78,55.68
GND on TOP (solid shape): 45.25,58.6 45.72,58.12 45.72,57.67 45.4,57.35 44.66,57.35 44.63,57.36 44.58,57.4 44.52,57.42 44.5,57.42 44.38,57.54 44.38,58.32 44.73,58.66 44.73,59.73 44.68,59.77 44.68,60.34 44.69,60.34 45.25,60.34
GND on TOP (solid shape): 67.23,27.81 68.61,27.81 68.68,27.74 68.68,27.33 68.48,27.13 66.57,27.13 66.45,27 66.45,25.7 66.37,25.63 65.63,25.63 65.56,25.7 65.56,27.84 65.7,27.98 67.07,27.98
GND on TOP (solid shape): 87.88,31.98 87.88,30.53 87.76,30.4 87.14,30.4 86.94,30.46 86.75,30.4 85.95,30.4 85.83,30.53 85.83,31.62 85.86,31.63 86.14,31.79 86.31,32.05 86.32,32.08 87.78,32.08
GND on TOP (solid shape): 21.54,60.43 21.54,59.78 21.48,59.72 20.95,59.72 20.85,59.62 20.85,57.84 20.69,57.68 20.63,57.68 20.61,57.69 20.49,57.78 20.35,57.81 20.28,57.8 20.21,57.78 20.18,57.77 19.9,58.05 19.59,58.05 19.52,58.11 19.52,58.78 19.58,58.83 19.66,58.83 19.81,58.99 19.81,59.2 21.08,60.47 21.49,60.47
GND on TOP (solid shape): 21.29,36.8 21.29,30.36 21.12,30.18 19.08,30.18 18.93,30.34 17.85,30.34 17.81,30.38 17.81,31.04 17.85,31.07 18.73,31.07 18.83,30.98 19.62,30.98 19.66,30.94 19.66,30.87 19.81,30.72 20.31,30.72 20.44,30.85 20.44,33.41 20.38,33.47 19.82,33.47 19.67,33.32 19.67,33.05 19.62,32.99 18.91,32.99 18.72,32.81 17.81,32.81 17.79,32.83 17.79,33.09 17.83,33.13 18.66,33.13 19.3,33.76 19.3,33.97 19.49,34.16 20.39,34.16 20.47,34.24 20.47,36.02 20.4,36.09 19.44,36.09 19.36,36.16 19.36,36.92 19.5,37.06 21.03,37.06
GND on TOP (solid shape): 146.56,40.49 146.59,40.44 146.59,8.71 146.45,8.36 146.1,8.22 134.07,8.22 133,7.78 132.56,6.71 132.56,3.56 132.05,3.56 132.05,6.71 132.64,8.14 134.07,8.73 146.08,8.73 146.08,13.77 146.11,14.04 146.11,14.31 146.11,14.58 146.08,14.85 146.08,31.73 146.08,31.74 146.08,32.49 146.08,32.49 145.97,32.59 143.28,32.59 143.21,32.66 143.21,33.66 143.26,33.71 145.95,33.71 146.08,33.84 146.08,40.06 146.3,40.26 146.5,40.47
GND on TOP (solid shape): 80.8,7.19 82.22,6.59 82.82,5.17 82.82,4.06 82.31,4.06 82.31,5.17 81.87,6.24 80.8,6.68 71.07,6.68 70,6.24 69.56,5.17 69.56,4.06 69.05,4.06 69.05,5.17 69.43,6.34 70.41,7.08 75.34,7.19
GND on TOP (solid shape): 100.51,63.39 100.86,63.25 101,62.9 101,52.08 100.86,51.94 100.65,51.94 100.49,52.1 100.49,54.86 100.39,54.96 100.01,54.96 99.82,55.15 99.82,55.77 99.67,55.92 99.67,56.95 99.52,57.1 98.26,57.1 98.21,57.15 98.21,57.95 98.27,58.01 100.26,58.01 100.49,58.25 100.49,62.64 100.25,62.88 88.03,62.88 88.03,51.44 87.43,50.01 86.01,49.42 78.51,49.42 78.51,49.93 86.01,49.93 87.08,50.37 87.52,51.44 87.52,62.9 87.66,63.25 88.01,63.39
GND on TOP (solid shape): 75.01,63.39 75.36,63.25 75.5,62.9 75.5,51.91 75.39,51.79 75.07,51.79 74.99,51.87 74.99,53.25 75.13,53.39 75.13,54.37 74.99,54.51 74.99,55.7 74.55,56.14 74.22,56.14 74.19,56.17 74.19,56.79 74.04,56.95 72.79,56.95 72.74,57 72.74,57.77 72.83,57.86 74.95,57.86 74.99,57.9 74.99,62.57 74.68,62.88 62.84,62.88 62.53,62.57 62.53,51.44 61.93,50.01 60.51,49.42 53.01,49.42 53.01,49.93 60.51,49.93 61.58,50.37 62.02,51.44 62.02,62.9 62.16,63.25 62.51,63.39
GND on TOP (solid shape): 49.51,63.39 49.86,63.25 50,62.9 50,51.43 50.04,51.1 50.15,50.78 49.6,50.78 49.52,51.1 49.49,51.44 49.49,56.08 49.42,56.16 48.77,56.16 48.67,56.26 48.67,56.77 48.51,56.92 47.25,56.92 47.22,56.95 47.22,57.78 47.28,57.84 49.2,57.84 49.49,58.14 49.49,62.54 49.15,62.88 37.36,62.88 37.03,62.55 37.03,51.44 36.44,50.01 35.01,49.42 27.51,49.42 27.51,49.93 35.01,49.93 36.08,50.37 36.52,51.44 36.52,62.9 36.66,63.25 37.01,63.39
GND on TOP (solid shape): 24.51,63.39 24.86,63.25 25,62.9 25,51.44 25.04,51.1 25.15,50.79 24.6,50.79 24.52,51.11 24.49,51.43 24.49,56.75 24.35,56.9 23.98,56.9 23.9,56.97 23.9,57.53 23.75,57.68 22.48,57.68 22.47,57.7 22.47,58.52 22.5,58.55 24.3,58.55 24.49,58.74 24.49,62.88 12.73,62.88 12.73,56.88 12.14,55.45 10.71,54.86 1.02,54.86 1.02,53.19 0.51,53.19 0.51,54.88 0.65,55.23 1,55.37 10.71,55.37 11.78,55.81 12.22,56.88 12.22,62.9 12.36,63.25 12.71,63.39
GND on TOP (solid shape): 146.1,63.39 146.45,63.25 146.59,62.9 146.59,39.65 146.08,39.65 146.08,62.34 145.54,62.88 117.5,62.88 117.03,62.41 117.03,56.88 116.46,55.48 115.09,54.87 115.07,54.87 114.72,54.99 114.34,55.04 113.96,54.99 113.6,54.86 113.03,54.86 113.03,54.39 112.77,53.91 112.68,53.38 112.77,52.84 113.03,52.37 113.03,51.44 112.44,50.01 111.01,49.42 104.15,49.42 104.01,49.56 104.01,49.56 104.01,49.82 104.11,49.93 111.01,49.93 112.08,50.37 112.52,51.44 112.52,54.88 112.66,55.23 113.01,55.37 115.01,55.37 116.08,55.81 116.52,56.88 116.52,62.9 116.66,63.25 117.01,63.39
GND on TOP (solid shape): outline of 201 points within 119.13,50.22 127.08,56.95
GND on BOTTOM (solid shape): 5.49,38.22 5.49,35 5.33,34.85 1.42,34.85 1.29,34.98 1.29,38.21 1.44,38.36 5.35,38.36
GND on BOTTOM (solid shape): 41.53,29.21 41.53,26.29 41.38,26.14 37.72,26.14 37.49,26.14 37.47,26.16 37.47,27.03 37.84,27.41 37.84,29.25 38.18,29.59 41.15,29.59
GND on BOTTOM (solid shape): 98.37,58.5 98.37,56.29 98.25,56.16 96.95,56.16 96.8,56.31 96.8,57.07 96.62,57.25 95.25,57.25 95.15,57.35 95.15,57.81 95.2,57.86 95.53,57.86 95.68,58.01 95.68,58.32 96.06,58.7 98.17,58.7
GND on BOTTOM (solid shape): 45.94,58.43 46.02,58.42 47.27,58.42 47.37,58.32 47.37,57.06 47.26,56.95 45.72,56.95 45.54,57.12 44.88,57.12 44.68,57.33 44.68,57.66 44.83,57.81 44.98,57.81 45.63,58.46 45.84,58.46
GND on BOTTOM (solid shape): 15.28,20.49 15.28,19.04 15.54,18.78 15.68,18.62 15.84,18.49 16.39,17.93 16.39,15.95 16.08,15.64 13.36,15.64 12.69,14.97 9.31,14.97 9.14,15.15 9.14,20.43 9.51,20.81 14.97,20.81
GND on BOTTOM (solid shape): 21.35,58.66 21.47,58.66 21.48,58.63 21.62,58.44 21.84,58.37 21.96,58.39 22.07,58.44 22.1,58.44 22.45,58.09 22.45,57 21.13,57 21.01,57.12 21.01,57.46 20.62,57.85 20.18,57.85 20.06,57.97 20.06,58.38 20.1,58.42 20.1,58.57 20.2,58.67 20.31,58.71 20.4,58.78 20.41,58.79 21.22,58.79
GND on BOTTOM (solid shape): 122.23,55.87 122.33,55.8 122.45,55.78 123.17,55.78 123.17,55.01 123.19,54.9 123.26,54.8 123.36,54.7 123.36,54.03 123.27,53.88 123.24,53.72 123.27,53.57 123.35,53.43 123.36,53.41 123.36,53.24 121.65,53.24 121.63,53.27 121.22,53.53 120.81,53.27 120.79,53.24 120.38,53.24 120.37,53.27 120.2,53.47 119.95,53.54 119.86,53.54 119.78,53.51 119.75,53.5 119.45,53.8 119.45,55.08 119.71,55.71 120.01,56.01 122.09,56.01
GND on BOTTOM (solid shape): 146.5,42.83 146.59,42.73 146.59,8.71 146.45,8.36 146.1,8.22 134.07,8.22 133,7.78 132.56,6.71 132.56,3.56 132.05,3.56 132.05,6.71 132.64,8.14 134.07,8.73 135.75,8.73 135.75,8.58 146.01,8.58 146.01,8.73 146.08,8.73 146.08,42.01 146.26,42.37 146.39,42.76
GND on BOTTOM (solid shape): 39.26,7.61 40.02,6.07 40.02,4.38 39.99,4.34 39.95,4.33 39.76,4.35 39.58,4.3 39.53,4.3 39.51,4.34 39.51,6.07 38.08,7.51 36.64,6.07 36.64,4.06 36.13,4.06 36.13,6.07 36.14,6.13 36.14,6.19 36.38,6.73 37.5,7.85 37.54,7.9 37.58,7.95
GND on BOTTOM (solid shape): outline of 144 points within 124.7,35.09 130.49,40.76
GND on BOTTOM (solid shape): outline of 537 points within 82.8,3.3 86.87,7.62
GND on BOTTOM (solid shape): outline of 582 points within 18.25,3.43 23.75,30.91
GND on BOTTOM (solid shape): outline of 146 points within 0.51,3.56 146.59,63.39
GND on GND (solid shape): outline of 2925 points within 0.51,3.05 146.59,63.39
GND on IN1 (solid shape): 146.5,42.8 146.59,42.7 146.59,8.71 146.45,8.36 146.1,8.22 134.07,8.22 133,7.78 132.56,6.71 132.56,3.56 132.05,3.56 132.05,6.71 132.64,8.14 134.07,8.73 146.08,8.73 146.08,13.77 146.11,14.04 146.11,14.31 146.11,14.58 146.08,14.85 146.08,41.99 146.26,42.35 146.39,42.73
GND on IN1 (solid shape): outline of 136 points within 0.51,3.56 146.59,63.39
GND on IN1 (solid shape): outline of 882 points within 119.56,42.48 125.4,55.91
GND on GND1 (solid shape): outline of 2713 points within 0.51,3.05 146.59,63.39
GND on VCC (solid shape): 114.66,37.26 114.73,37.23 114.76,37.16 114.76,36.35 114.4,36.2 114.32,36.15 114.24,36.09 113.05,34.9 112.94,34.88 112.88,34.98 112.88,35.81 114.33,37.26 114.63,37.26
GND on VCC (solid shape): 36.65,38.53 36.81,38.42 37.01,38.38 38.57,38.38 38.59,38.37 38.61,38.32 38.57,38.27 38.5,38.26 38.43,38.24 37.27,37.76 37.19,37.71 37.11,37.65 36.54,37.08 36.45,37.06 36.36,37.08 36.32,37.16 36.32,38.3 36.6,38.57
GND on VCC (solid shape): 118.67,50.82 118.67,50.75 118.68,50.62 118.73,50.5 118.73,49.87 118.69,49.78 118.6,49.77 118.55,49.78 118.49,49.78 118.22,49.67 118.11,49.4 118.11,49.35 118.13,49.28 118.13,49.23 118.03,49.23 117.84,49.19 117.67,49.08 117.01,48.42 116.9,48.39 116.84,48.49 116.84,49.6 117.3,50.06 117.41,50.22 117.45,50.42 117.45,50.82 117.66,51.03 118.46,51.03
GND on VCC (solid shape): 113.95,45.61 113.94,45.53 113.94,44.15 113.98,43.96 114.09,43.79 114.63,43.25 114.63,41.84 113.45,40.67 111.87,40.67 111,41.53 110.84,41.64 110.64,41.68 108.55,41.68 108.47,41.73 108.46,41.82 108.48,41.89 108.48,41.96 108.47,42.04 108.45,42.12 108.46,42.22 108.54,42.27 109.32,42.27 109.52,42.3 109.68,42.41 112.04,44.77 112.79,44.77 112.98,44.81 113.15,44.92 113.89,45.67
GND on VCC (solid shape): 116.35,50.71 116.4,50.72 116.43,50.67 116.43,50.63 115.97,50.17 115.86,50 115.82,49.81 115.82,47.81 115.33,47.32 114.32,47.32 114.26,47.32 114.15,47.37 114.17,47.49 114.31,47.62 114.33,47.63 114.67,47.78 114.81,48.13 114.66,48.49 114.3,48.64 114.23,48.64 114.18,48.67 114.19,48.73 114.92,49.45 114.94,49.46 115.1,49.5 115.24,49.6
GND on VCC (solid shape): 92.94,30.35 93.04,30.29 93.02,30.19 92.96,30.07 92.94,29.95 93.05,29.68 93.32,29.57 93.41,29.5 93.39,29.39 92.8,28.8 91.92,28.8 91.84,28.84 91.82,28.92 91.82,28.98 91.44,29.36 91.06,28.98 91.06,28.92 91.04,28.84 90.96,28.8 88.38,28.8 88.29,28.87 88.31,28.98 89.68,30.35
GND on VCC (solid shape): 106.16,27.43 106.25,27.38 106.24,27.27 107.06,25.72 107.71,27.35 107.7,27.36 107.7,27.43 107.87,27.43 108.38,26.92 108.54,26.81 108.74,26.77 111.4,26.77 111.44,26.77 111.5,26.78 111.56,26.73 108.86,24.03 105.85,24.03 103.98,25.9 103.95,26.01 104.05,26.08 104.44,26.08 104.63,26.11 104.8,26.23 106,27.43
GND on VCC (solid shape): outline of 146 points within 62.81,26.97 67.53,29.97
GND on VCC (solid shape): outline of 1136 points within 48.16,22.58 85.94,38.91
GND on VCC (solid shape): outline of 1762 points within 75.02,27.09 113.53,40.46
GND on GND2 (solid shape): outline of 2713 points within 0.51,3.05 146.59,63.39
GND on IN2 (solid shape): 123.25,55.77 123.32,55.75 123.36,55.67 123.36,53.89 123.35,53.88 123.32,53.72 123.35,53.56 123.36,53.55 123.36,53.23 121.57,53.23 121.22,53.45 120.87,53.23 120.31,53.23 120.29,53.26 119.95,53.47 119.61,53.26 119.6,53.23 119.47,53.23 119.47,54.89 119.7,55.12 119.77,55.23 119.8,55.35 119.8,55.7 119.86,55.77 123.22,55.77
GND on IN2 (solid shape): 146.5,42.8 146.59,42.7 146.59,8.71 146.45,8.36 146.1,8.22 134.07,8.22 133,7.78 132.56,6.71 132.56,3.56 132.05,3.56 132.05,6.71 132.64,8.14 134.07,8.73 146.08,8.73 146.08,13.77 146.11,14.04 146.11,14.31 146.11,14.58 146.08,14.85 146.08,41.99 146.26,42.35 146.39,42.73
GND on IN2 (solid shape): outline of 139 points within 0.51,3.56 146.59,63.39
GND on GND3 (solid shape): outline of 2779 points within 0.51,3.05 146.59,63.39
GND1 on GND (solid shape): outline of 5373 points within -60.49,0.51 9.2,129.29
GND1 on GND1 (solid shape): outline of 4731 points within -60.49,0.51 9.2,129.29
GND1 on VCC (solid shape): outline of 6235 points within -60.49,0.51 9.2,129.29
GND1 on VCC1 (solid shape): outline of 4731 points within -60.49,0.51 9.2,129.29
GND1 on GND2 (solid shape): outline of 4731 points within -60.49,0.51 9.2,129.29
GND1 on GND3 (solid shape): outline of 5367 points within -60.49,0.51 9.2,129.29
P1V2_STBY on TOP (solid shape): 121.93,26.17 123.23,26.17 123.44,25.96 123.44,24.36 123.39,24.31 122.43,24.31 122.3,24.43 118.82,24.43 118.62,24.64 118.62,26.01 118.78,26.17 121.92,26.17
P1V2_STBY on BOTTOM (solid shape): 117.24,40.64 117.84,40.64 118.36,40.64 118.49,40.51 118.49,39.5 118.36,39.37 116.97,39.37 116.84,39.5 116.84,39.73 116.94,40.01 116.84,40.29 116.84,40.51 116.97,40.64 117.2,40.64
P1V2_STBY on BOTTOM (solid shape): 128.81,34.99 128.81,34.73 128.75,34.65 128.72,34.56 128.71,34.55 128.17,34 128.15,34 128,33.92 127.92,33.76 127.91,33.75 127.49,33.32 127.27,33.32 126.97,33.32 126.41,33.88 126.41,34.6 126.93,35.11 127.89,35.11 128.01,34.99 128.36,34.99 128.49,35.12 128.69,35.12
P1V2_STBY on BOTTOM (solid shape): 126.71,41.13 126.75,41.1 126.9,40.98 127.15,40.98 127.32,41.15 127.49,41.15 127.66,40.98 127.91,40.98 128.03,41.1 128.05,41.11 128.09,41.15 129.29,41.15 129.51,40.92 129.51,40.9 129.55,40.75 129.67,40.63 129.67,40.42 128.09,40.42 128.05,40.39 128.02,40.39 127.89,40.26 127.89,39.88 127.76,39.75 127.13,39.75 127,39.88 127,40.39 126.87,40.51 126.62,40.51 126.52,40.41 126.46,40.41 126.36,40.31 126.07,40.31 125.98,40.4 125.98,40.65 126.08,40.75 126.12,40.89 126.15,40.96 126.22,40.98 126.34,40.98 126.47,41.11 126.51,41.15 126.69,41.15
P1V2_STBY on BOTTOM (solid shape): 131.67,39.35 131.67,38.79 131.68,38.73 131.7,38.69 131.71,38.68 131.71,38.06 131.66,37.97 131.56,37.97 131.49,38 131.42,38.01 131.2,37.92 131.11,37.7 131.15,37.55 131.26,37.44 131.31,37.36 131.28,37.28 131.24,37.24 131.24,37.21 130.71,36.69 130.54,36.69 130.46,36.78 130.45,36.79 130.44,36.81 130.44,36.99 130.53,37.08 130.54,37.09 130.54,37.11 130.54,37.16 130.72,37.16 130.82,37.22 130.82,37.4 130.72,37.46 130.57,37.46 130.54,37.49 129.98,38.06 129.96,38.07 129.94,38.07 129.82,38.07 129.82,38.86 129.93,38.97 129.94,38.97 130.33,39.35 130.35,39.35 130.37,39.36 130.52,39.51 131.52,39.51
P1V2_STBY on BOTTOM (solid shape): 122.56,49.07 122.56,48.78 122.5,48.69 122.4,48.7 122.29,48.75 122.17,48.77 121.79,48.39 122.17,48.01 122.29,48.02 122.4,48.08 122.5,48.08 122.56,47.99 122.56,46.71 122.46,46.61 122.39,46.61 122.37,46.62 122.28,46.67 122.17,46.69 122.06,46.67 121.96,46.61 120.9,46.61 120.78,46.74 120.78,47.1 120.85,47.23 120.88,47.37 120.86,47.51 120.79,47.63 120.78,47.64 120.78,47.69 120.79,47.7 120.89,47.84 120.93,48.01 120.89,48.18 120.78,48.32 120.78,48.43 120.79,48.45 120.84,48.55 120.85,48.66 120.84,48.78 120.79,48.88 120.78,48.89 120.78,48.98 120.86,49.06 120.95,49.19 120.99,49.35 120.99,49.37 121.03,49.4 122.22,49.4
P1V2_STBY on VCC (solid shape): outline of 7629 points within 116.96,25.07 133.35,49.33
P3V3_AUX on TOP (solid shape): 46.99,35.94 46.99,33.78 46.86,33.66 44.2,33.66 44.07,33.78 44.07,35.18 44.2,35.31 44.96,35.31 45.21,35.56 45.21,35.94 45.34,36.07 46.86,36.07
P3V3_AUX on TOP (solid shape): 127.8,55.43 128.04,55.34 128.29,55.43 128.78,55.43 128.9,55.31 128.9,54.35 128.65,54.1 127.38,54.1 127.25,54.23 127.25,55.22 127.36,55.29 127.44,55.4 127.45,55.43
P3V3_AUX on TOP (solid shape): 65.3,26.29 65.3,24.49 65.09,24.27 64.6,24.27 64.24,23.9 64.24,23.37 63.99,23.12 63.99,22.69 64.45,22.23 66.59,22.23 66.65,22.17 66.65,22.01 66.6,21.96 64.62,21.96 64.52,21.86 64.52,21.39 64.68,21.22 66.05,21.22 66.08,21.2 66.08,20.99 66.01,20.93 65.12,20.93 65.07,20.88 65.07,20.57 64.91,20.41 63.7,20.41 63.43,20.68 62.84,20.68 62.74,20.79 62.74,22.14 62.41,22.46 62.41,25.42 62.61,25.61 62.61,26.22 62.78,26.39 65.2,26.39
P3V3_AUX on TOP (solid shape): 127.74,25.81 127.74,25.43 128.37,24.79 128.37,23.55 128.36,23.53 128.36,23.42 128.92,22.86 128.92,20.34 128.91,20.33 128.91,19.71 128.32,19.11 128.32,16.74 128.24,16.66 128.17,16.66 128.07,16.76 128.07,18.54 127.94,18.67 127.43,18.67 127.3,18.54 127.3,17.2 127.28,17.17 127.1,17.17 127.03,17.25 127.03,18.59 126.54,19.08 125.86,19.08 125.68,18.9 125.68,17.42 125.4,17.14 122.19,17.14 122.06,17.27 122.06,18.12 122,18.19 121.56,18.19 121.56,19.27 122.76,20.46 124.83,20.46 126.92,22.56 126.92,23.8 126.77,23.95 125.63,23.95 125.63,25.76 125.73,25.86 127.69,25.86
P3V3_AUX on TOP (solid shape): 13.67,45.24 13.67,43.43 13.49,43.26 13.21,43.26 12.78,42.82 12.78,42.29 12.53,42.05 12.53,41.61 12.99,41.15 15.13,41.15 15.19,41.09 15.19,40.93 15.14,40.89 13.16,40.89 13.05,40.78 13.05,40.31 13.22,40.15 14.59,40.15 14.62,40.12 14.62,39.92 14.55,39.85 13.66,39.85 13.61,39.8 13.61,39.5 13.45,39.33 11.21,39.33 11.17,39.37 11.17,39.93 10.57,40.53 9.57,40.53 9.42,40.68 9.42,42.11 9.55,42.24 10.95,42.24 11.02,42.32 11.02,44.02 11.2,44.2 11.99,44.2 13.08,45.29 13.61,45.29
P3V3_AUX on TOP (solid shape): 42.39,43.1 42.39,41.27 41.86,40.74 41.86,40.21 41.61,39.96 41.61,39.53 42.08,39.07 44.21,39.07 44.27,39.01 44.27,38.85 44.22,38.8 42.25,38.8 42.14,38.7 42.14,38.23 42.3,38.06 43.68,38.06 43.7,38.04 43.7,37.83 43.63,37.77 42.74,37.77 42.7,37.72 42.7,37.41 42.53,37.25 41.99,37.25 40.7,35.97 37.85,35.97 37.69,36.12 37.69,37.13 38.51,37.95 38.51,39.47 38.56,39.53 39.5,39.53 39.59,39.49 39.69,39.48 39.97,39.59 40.08,39.87 40.05,40.01 39.98,40.13 39.98,43 40.08,43.1 41.43,43.1 41.53,43.21 42.29,43.21
P3V3_AUX on TOP (solid shape): 89.79,34.16 89.79,33.78 90.07,33.5 90.07,33.33 90.05,33.24 90.04,33.17 90.09,32.95 90.23,32.77 90.25,32.75 90.39,32.68 90.55,32.66 91.17,32.66 91.33,32.69 91.48,32.77 92.53,32.77 92.63,32.66 92.63,31.57 90.99,29.93 90.99,28.84 91.45,28.38 93.59,28.38 93.72,28.5 94.09,28.5 94.21,28.38 94.21,28.12 94.1,28 93.71,28 93.6,28.11 91.62,28.11 91.52,28 91.52,27.53 91.68,27.37 93.05,27.37 93.08,27.34 93.08,27.14 93.01,27.07 92.12,27.07 92.08,27.03 92.08,26.72 91.91,26.55 88.95,26.55 88.75,26.75 88.75,28.59 88.14,29.21 88.14,34.04 88.39,34.29 89.66,34.29
P3V3_AUX on BOTTOM (solid shape): 126.11,46.08 126.11,45.19 126.03,45.11 125.99,45.06 125.96,44.99 125.95,44.96 124.72,44.96 124.72,46 125.07,46.35 125.38,46.35 125.5,46.37 125.6,46.44 125.65,46.48 125.7,46.48
P3V3_AUX on BOTTOM (solid shape): 118.14,35.69 118.14,34.82 118.06,34.75 117.98,34.77 117.93,34.77 117.87,34.77 117.79,34.75 116.1,34.75 116.03,34.82 116,34.88 116,35.59 116.19,35.78 116.32,35.7 116.46,35.67 116.63,35.71 116.76,35.81 118.01,35.81
P3V3_AUX on BOTTOM (solid shape): 123.77,40.2 123.77,39.21 124.03,38.95 124.94,38.95 125.13,38.77 125.13,38.1 125.03,38.01 124.97,38 124.26,38 124.17,38 123.46,38 123.37,38 123.13,38 123.03,38.1 123.03,39.31 123.12,39.39 123.14,39.39 123.33,39.57 123.33,39.83 123.16,40 123.16,40 123.16,40.21 123.33,40.37 123.6,40.37
P3V3_AUX on IN1 (solid shape): outline of 1664 points within 8.59,34.95 47.52,45.87
P3V3_AUX on VCC1 (solid shape): outline of 3673 points within 1.02,3.05 146.08,62.88
P3V3_DB800 on BOTTOM (solid shape): 41.69,32.1 41.69,30.21 41.61,30.13 39.61,30.13 39.55,30.18 39.55,30.93 39.65,31.06 39.68,31.22 39.57,31.49 39.3,31.6 39.26,31.6 39.2,31.59 39.14,31.65 39.14,32.12 39.18,32.16 41.63,32.16
P3V3_E1S_0 on TOP (solid shape): 15.85,44.63 15.85,44.22 16.13,43.94 16.13,43.79 16.43,43.48 18.29,43.48 18.85,42.93 19.18,42.93 22.23,39.88 23.67,39.88 24.43,39.12 26.92,39.12 27.33,38.71 28.8,38.71 28.88,38.63 28.88,38.33 28.84,38.29 27.5,38.29 27.3,38.1 21.97,38.1 20.04,40.03 18.57,40.03 18.3,40.3 17.36,40.3 17.32,40.34 13.4,40.34 13.34,40.4 13.34,40.66 13.36,40.68 15.26,40.68 15.41,40.83 15.41,41.18 15.22,41.37 13.88,41.37 13.84,41.41 13.84,41.63 13.93,41.71 15.32,41.71 15.47,41.86 15.47,42.67 15.09,43.05 15.09,44.75 15.11,44.78 15.7,44.78
